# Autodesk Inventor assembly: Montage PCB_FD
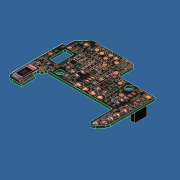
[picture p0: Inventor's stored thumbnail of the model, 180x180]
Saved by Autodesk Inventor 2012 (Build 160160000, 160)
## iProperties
Created: 2011-10
Part Number: Montage PCB_FD
Document SubType Name: Assembly
Designer: Laur
Author: Laur
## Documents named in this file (3)
- D:\Formulaire\Sujet CIM 2012\Modélisation_7970_shimano\Montage PCB_FD.iam
- D:\Formulaire\Sujet CIM 2012\Modélisation_7970_shimano\PCB_FD.ipt
- D:\Formulaire\Sujet CIM 2012\Modélisation_7970_shimano\capteur opto.ipt
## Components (2 placed, 2 different names)
1. PCB_FD:1 — pos capteur / pcb
2. capteur opto:1 — pos capteur / pcb
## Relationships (1: Flush 1)
- pos capteur / pcb [Flush]: PCB_FD:1 ↔ capteur opto:1
